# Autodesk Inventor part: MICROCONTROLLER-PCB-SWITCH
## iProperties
Created: 2007-09
Part Number: MICROCONTROLLER-PCB-SWITCH
Document SubType Name: Modeling
Density: 1 g/cm^3
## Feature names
1. Base1
